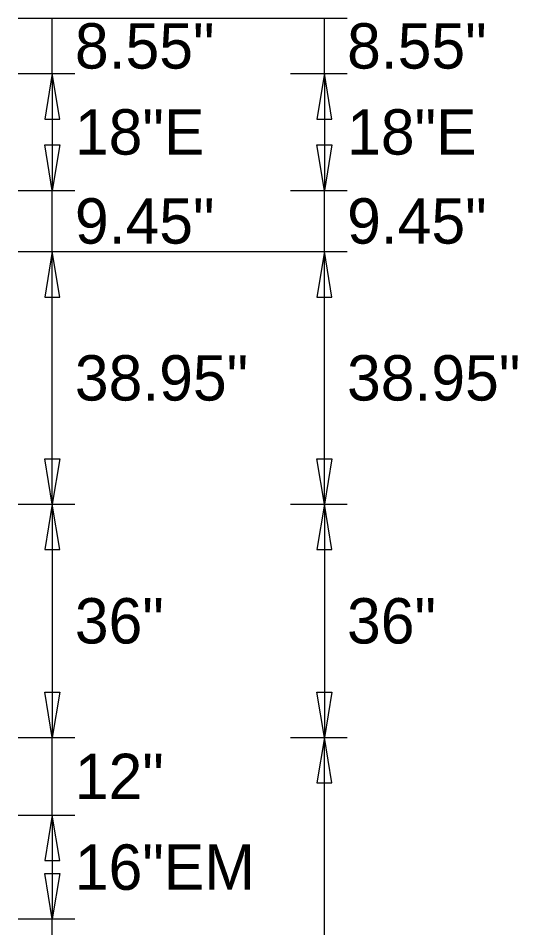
# Model space of a CAD drawing. Extents: x 2149961 to 2150220, y 145114 to 145240.
# Drawn here: x 2150047.75 to 2150054.17, y 145199 to 145210.69 of the extents above; entities that cross this region are included whole.
import ezdxf

# ---------------------------------------------------------------- set-up
doc = ezdxf.new("R2010")
doc.units = 0
doc.layers.add('GSDIMS', color=7, linetype='Continuous')

msp = doc.modelspace()

# ---------------------------------------------------------------- linework, layer by layer
at = {"layer": 'GSDIMS'}
for p, q in [((2150047.749, 145210.695), (2150048.479, 145210.695)), ((2150047.749, 145210.695), (2150051.249, 145210.695)), ((2150048.187, 145209.982), (2150048.187, 145210.695)), ((2150051.249, 145210.695), (2150051.979, 145210.695)), ((2150051.687, 145209.982), (2150051.687, 145210.695)), ((2150047.749, 145209.982), (2150048.479, 145209.982)), ((2150047.749, 145209.982), (2150048.479, 145209.982)), ((2150048.187, 145209.982), (2150048.187, 145208.482)), ((2150051.249, 145209.982), (2150051.979, 145209.982)), ((2150051.249, 145209.982), (2150051.979, 145209.982)), ((2150051.687, 145209.982), (2150051.687, 145208.482)), ((2150047.749, 145208.482), (2150048.479, 145208.482)), ((2150047.749, 145208.482), (2150048.479, 145208.482)), ((2150048.187, 145207.695), (2150048.187, 145208.482)), ((2150051.249, 145208.482), (2150051.979, 145208.482)), ((2150051.249, 145208.482), (2150051.979, 145208.482)), ((2150051.687, 145207.695), (2150051.687, 145208.482)), ((2150047.749, 145207.695), (2150048.479, 145207.695)), ((2150047.749, 145207.695), (2150051.249, 145207.695)), ((2150047.749, 145207.695), (2150048.478, 145207.695)), ((2150047.749, 145207.695), (2150051.249, 145207.695)), ((2150048.187, 145204.449), (2150048.187, 145207.695)), ((2150051.249, 145207.695), (2150051.979, 145207.695)), ((2150051.249, 145207.695), (2150051.978, 145207.695)), ((2150051.687, 145204.449), (2150051.687, 145207.695)), ((2150047.749, 145204.449), (2150048.478, 145204.449)), ((2150047.749, 145204.449), (2150048.478, 145204.449)), ((2150048.187, 145204.449), (2150048.187, 145201.449)), ((2150051.249, 145204.449), (2150051.978, 145204.449)), ((2150051.249, 145204.449), (2150051.978, 145204.449)), ((2150051.687, 145204.449), (2150051.687, 145201.449)), ((2150047.749, 145201.449), (2150048.478, 145201.449)), ((2150047.749, 145201.449), (2150048.478, 145201.449)), ((2150048.187, 145200.449), (2150048.187, 145201.449)), ((2150051.249, 145201.449), (2150051.978, 145201.449)), ((2150051.249, 145201.449), (2150051.978, 145201.449)), ((2150051.687, 145193.195), (2150051.687, 145201.449)), ((2150047.749, 145200.449), (2150048.478, 145200.449)), ((2150047.749, 145200.449), (2150048.478, 145200.449)), ((2150048.187, 145200.449), (2150048.187, 145199.116)), ((2150047.749, 145199.116), (2150048.478, 145199.116)), ((2150047.749, 145199.116), (2150048.478, 145199.116)), ((2150048.187, 145198.116), (2150048.187, 145199.116))]:
    msp.add_line(p, q, dxfattribs=at)
for points in [[(2150048.187, 145209.982), (2150048.09, 145209.399), (2150048.284, 145209.399)], [(2150051.687, 145209.982), (2150051.59, 145209.399), (2150051.784, 145209.399)], [(2150048.187, 145208.482), (2150048.09, 145209.066), (2150048.284, 145209.066)], [(2150051.687, 145208.482), (2150051.59, 145209.066), (2150051.784, 145209.066)], [(2150048.187, 145207.695), (2150048.09, 145207.111), (2150048.284, 145207.111)], [(2150051.687, 145207.695), (2150051.59, 145207.111), (2150051.784, 145207.111)], [(2150048.187, 145204.449), (2150048.09, 145205.032), (2150048.284, 145205.032)], [(2150051.687, 145204.449), (2150051.59, 145205.032), (2150051.784, 145205.032)], [(2150048.187, 145204.449), (2150048.09, 145203.866), (2150048.284, 145203.866)], [(2150051.687, 145204.449), (2150051.59, 145203.866), (2150051.784, 145203.866)], [(2150048.187, 145201.449), (2150048.09, 145202.032), (2150048.284, 145202.032)], [(2150051.687, 145201.449), (2150051.59, 145202.032), (2150051.784, 145202.032)], [(2150051.687, 145201.449), (2150051.59, 145200.866), (2150051.784, 145200.866)], [(2150048.187, 145200.449), (2150048.09, 145199.866), (2150048.284, 145199.866)], [(2150048.187, 145199.116), (2150048.09, 145199.699), (2150048.284, 145199.699)]]:
    msp.add_lwpolyline(points, close=True, dxfattribs=at)

# ---------------------------------------------------------------- texts
for s, p in [('8.55"', (2150048.479, 145210.047)), ('8.55"', (2150051.979, 145210.047)), ('18"E', (2150048.479, 145208.941)), ('18"E', (2150051.979, 145208.941)), ('9.45"', (2150048.479, 145207.797)), ('9.45"', (2150051.979, 145207.797)), ('38.95"', (2150048.478, 145205.78)), ('38.95"', (2150051.978, 145205.78)), ('36"', (2150048.478, 145202.657)), ('36"', (2150051.978, 145202.657)), ('12"', (2150048.478, 145200.657)), ('16"EM', (2150048.478, 145199.491))]:
    msp.add_text(s, height=0.5833, dxfattribs=at).set_placement(p)

doc.saveas('drawing.dxf')
